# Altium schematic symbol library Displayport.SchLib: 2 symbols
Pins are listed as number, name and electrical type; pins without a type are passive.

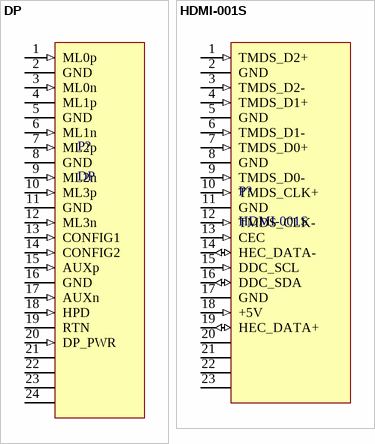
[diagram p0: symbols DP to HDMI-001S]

## DP
designator P?
footprint CAR06-201EN5F
pins: 1 ML0p (in), 2 GND, 3 ML0n (in), 4 ML1p, 5 GND, 6 ML1n (in), 7 ML2p (in), 8 GND, 9 ML2n (in), 10 ML3p (in), 11 GND, 12 ML3n (in), 13 CONFIG1 (in), 14 CONFIG2 (in), 15 AUXp (in), 16 GND, 17 AUXn (in), 18 HPD (in), 19 RTN, 20 DP_PWR (in), 21, 22, 23, 24

## HDMI-001S
designator P?
footprint HDMI-001S
pins: 1 TMDS_D2+ (in), 2 GND, 3 TMDS_D2- (in), 4 TMDS_D1+ (in), 5 GND, 6 TMDS_D1- (in), 7 TMDS_D0+ (in), 8 GND, 9 TMDS_D0- (in), 10 TMDS_CLK+ (in), 11 GND, 12 TMDS_CLK- (in), 13 CEC (in), 14 HEC_DATA- (io), 15 DDC_SCL (in), 16 DDC_SDA (io), 17 GND, 18 +5V (in), 19 HEC_DATA+ (io), 20, 21, 22, 23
